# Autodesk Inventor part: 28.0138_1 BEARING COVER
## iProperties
Created: 2007-06
Part Number: 28.0138_1 BEARING COVER
Document SubType Name: Modeling
Designer: Andy Moles
Material: Aluminum-6061
Mass: 12.1383 g
Surface Area: 65.103 cm^2
Volume: 4.47906 cm^3
Density: 2.71 g/cm^3
Author: Andy Moles
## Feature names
1. Extrusion1
2. Extrusion2
